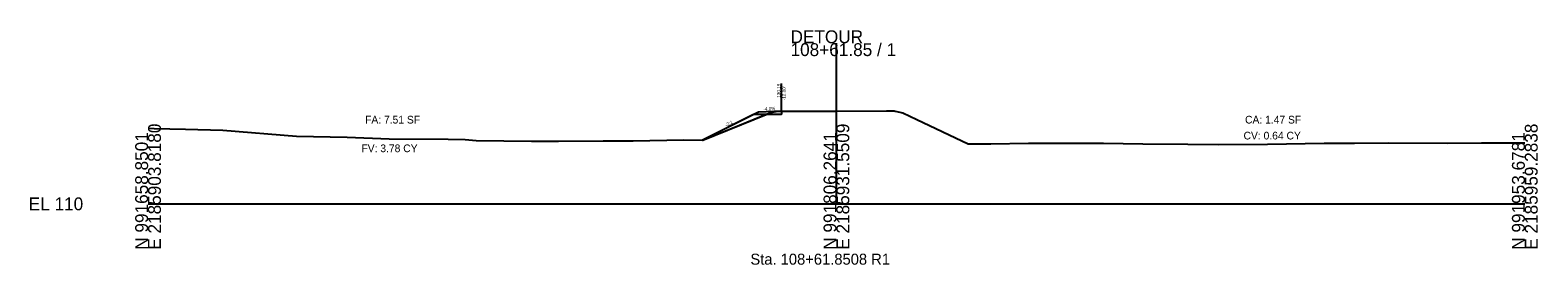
# Model space of a CAD drawing. Extents: x -3604 to 2303, y -13 to 9543.
# Drawn here: x 1974.3 to 2302.8, y 2986.7 to 3037.8 of the extents above; entities that cross this region are included whole.
import ezdxf

# ---------------------------------------------------------------- set-up
doc = ezdxf.new("R2010")
doc.units = 0
for name, color, linetype in [('Draft_XS_Grid', 7, 'Continuous'), ('Draft_XS_Text', 7, 'Continuous'), ('DTM_X_GROUND', 7, 'Continuous'), ('XS_CELL', 7, 'Continuous'), ('XS_M_SHAPES_EARTHWORK', 7, 'Continuous'), ('XS_P_ASPHALT', 7, 'Continuous'), ('XS_P_GROUND', 7, 'Continuous'), ('XS_P_TX_CLEARZONE', 7, 'Continuous'), ('XS_P_TX_FS_BS', 7, 'Continuous'), ('XS_SHEET_EW_TX_AREA', 7, 'Continuous'), ('XS_SHEET_EW_TX_VOLUME', 7, 'Continuous')]:
    doc.layers.add(name, color=color, linetype=linetype)

msp = doc.modelspace()

# ---------------------------------------------------------------- linework, layer by layer
at = {"layer": 'DTM_X_GROUND'}
msp.add_lwpolyline([(2000, 3016.48), (2001.33, 3016.45), (2008.16, 3016.25), (2016.27, 3016.05), (2032.33, 3014.78), (2043.36, 3014.53), (2052.53, 3014.19), (2065.4, 3014.08), (2069.07, 3013.99), (2071.47, 3013.79), (2083.55, 3013.64), (2089.46, 3013.64), (2099.17, 3013.75), (2105.67, 3013.73), (2116.66, 3013.92), (2120.9, 3013.91), (2135.25, 3019.73), (2135.64, 3019.89), (2135.68, 3019.89), (2137.23, 3020.18), (2146.13, 3020.22), (2149.82, 3020.23), (2160.94, 3020.27), (2162.55, 3020.27), (2162.79, 3020.22), (2164.46, 3019.84), (2167.53, 3018.36), (2178.74, 3013.06), (2183.65, 3013.09), (2191.88, 3013.23), (2201.34, 3013.21), (2208.17, 3013.22), (2216.76, 3013.1), (2226.55, 3012.99), (2233.19, 3012.9), (2243.96, 3012.97), (2256.25, 3013.19), (2262.92, 3013.21), (2270.24, 3013.28), (2283.08, 3013.19), (2290.58, 3013.26), (2300, 3013.26)], dxfattribs=at)
msp.add_lwpolyline([(2000, 3016.48), (2001.33, 3016.45), (2008.16, 3016.25), (2016.27, 3016.05), (2032.33, 3014.78), (2043.36, 3014.53), (2052.53, 3014.19), (2065.4, 3014.08), (2069.07, 3013.99), (2071.47, 3013.79), (2083.55, 3013.64), (2089.46, 3013.64), (2099.17, 3013.75), (2105.67, 3013.73), (2116.66, 3013.92), (2120.9, 3013.91), (2135.25, 3019.73), (2135.64, 3019.89), (2135.68, 3019.89), (2137.23, 3020.18), (2146.13, 3020.22), (2149.82, 3020.23), (2160.94, 3020.27), (2162.55, 3020.27), (2162.79, 3020.22), (2164.46, 3019.84), (2167.53, 3018.36), (2178.74, 3013.06), (2183.65, 3013.09), (2191.88, 3013.23), (2201.34, 3013.21), (2208.17, 3013.22), (2216.76, 3013.1), (2226.55, 3012.99), (2233.19, 3012.9), (2243.96, 3012.97), (2256.25, 3013.19), (2262.92, 3013.21), (2270.24, 3013.28), (2283.08, 3013.19), (2290.58, 3013.26), (2300, 3013.26)], dxfattribs=at)
at = {"layer": 'XS_CELL'}
for p, q in [((2150, 3000), (2150, 3035)), ((2000, 3000), (2150, 3000)), ((2150, 3000), (2300, 3000))]:
    msp.add_line(p, q, dxfattribs=at)
at = {"layer": 'XS_M_SHAPES_EARTHWORK'}
for points in [[(2120.85, 3013.91), (2120.9, 3013.91), (2134.68, 3019.5), (2131.91, 3019.44)], [(2134.68, 3019.5), (2135.25, 3019.73), (2135.64, 3019.89), (2135.68, 3019.89), (2137.23, 3020.18), (2138, 3020.19), (2138, 3019.56)]]:
    msp.add_lwpolyline(points, close=True, dxfattribs=at)
at = {"layer": 'XS_P_ASPHALT'}
for points in [[(2131.91, 3019.44), (2138, 3019.56)], [(2138, 3020.19), (2138, 3019.56)], [(2138, 3020.19), (2138, 3019.56)]]:
    msp.add_lwpolyline(points, dxfattribs=at)
at = {"layer": 'XS_P_GROUND'}
for points in [[(2133, 3019.99), (2120.85, 3013.91)], [(2138, 3020.19), (2133, 3019.99)]]:
    msp.add_lwpolyline(points, dxfattribs=at)
at = {"layer": 'XS_P_TX_CLEARZONE'}
msp.add_line((2138, 3020.19), (2138, 3026.19), dxfattribs=at)

# ---------------------------------------------------------------- texts
at = {"layer": 'Draft_XS_Grid'}
msp.add_text('-', height=0.0001, dxfattribs=at).set_placement((2000, 3000))
at = {"layer": 'Draft_XS_Text'}
msp.add_text('Sta. 108+61.8508 R1', height=2.4, dxfattribs=at).set_placement((2131.25, 2986.75))
at = {"layer": 'XS_CELL'}
for s, p in [('DETOUR', (2140, 3035)), ('108+61.85 / 1', (2140, 3032.2)), ('EL 110', (1974, 2998.6))]:
    msp.add_text(s, height=2.8, dxfattribs=at).set_placement(p)
for s, p in [('E 2185903.8180', (2002.8, 2990)), ('E 2185931.5509', (2152.8, 2990)), ('E 2185959.2838', (2302.8, 2990)), ('N 991658.8501', (2000, 2990)), ('N 991806.2641', (2150, 2990)), ('N 991953.6781', (2300, 2990))]:
    msp.add_text(s, height=2.8, rotation=90, dxfattribs=at).set_placement(p)
at = {"layer": 'XS_P_ASPHALT'}
for p in [(2131.87, 3019.38), (2137.96, 3020.13), (2137.96, 3020.13), (2137.96, 3019.5), (2137.96, 3019.5)]:
    msp.add_text('X', height=0.12, dxfattribs=at).set_placement(p)
at = {"layer": 'XS_P_GROUND'}
msp.add_text('X', height=0.12, dxfattribs=at).set_placement((2120.81, 3013.85))
at = {"layer": 'XS_P_TX_CLEARZONE'}
for s, p in [('130.19', (2137.76, 3023.11)), ("-12.00'", (2138.96, 3022.58))]:
    msp.add_text(s, height=0.72, rotation=90, dxfattribs=at).set_placement(p)
at = {"layer": 'XS_P_TX_FS_BS'}
for s, rotation, p in [('-4.0%', 2.2906, (2134.09, 3020.33)), ('-2:1', 26.5651, (2125.98, 3016.81))]:
    msp.add_text(s, height=0.72, rotation=rotation, dxfattribs=at).set_placement(p)
at = {"layer": 'XS_SHEET_EW_TX_AREA'}
for s, p in [('FA: 7.51 SF', (2047.29, 3017.5)), ('CA: 1.47 SF', (2239.04, 3017.5))]:
    msp.add_text(s, height=1.68, dxfattribs=at).set_placement(p)
at = {"layer": 'XS_SHEET_EW_TX_VOLUME'}
for s, p in [('FV: 3.78 CY', (2046.49, 3011.26)), ('CV: 0.64 CY', (2238.71, 3014.03))]:
    msp.add_text(s, height=1.68, dxfattribs=at).set_placement(p)

doc.saveas('drawing.dxf')
